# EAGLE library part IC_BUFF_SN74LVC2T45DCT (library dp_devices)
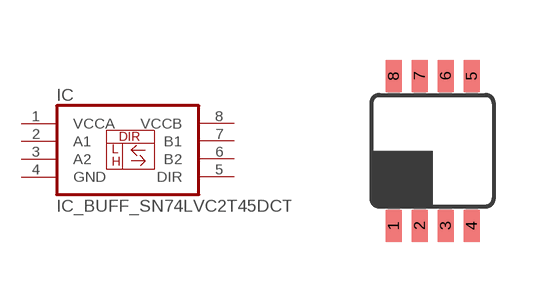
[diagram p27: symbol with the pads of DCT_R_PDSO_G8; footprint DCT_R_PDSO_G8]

Designator prefix IC

## IC_BUFF_SN74LVC2T45DCT  [DCT_R_PDSO_G8]
1  VCCA  pwr
2  A1
3  A2
4  GND  pwr
5  DIR  in
6  B2
7  B1
8  VCCB  pwr

## Footprint DCT_R_PDSO_G8 (pad centres in mm)
smd 0.4 x 0.8: 1 -0.975,-1.875; 2 -0.325,-1.875; 3 0.325,-1.875; 4 0.975,-1.875; 5 0.975,1.875; 6 0.325,1.875; 7 -0.325,1.875; 8 -0.975,1.875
